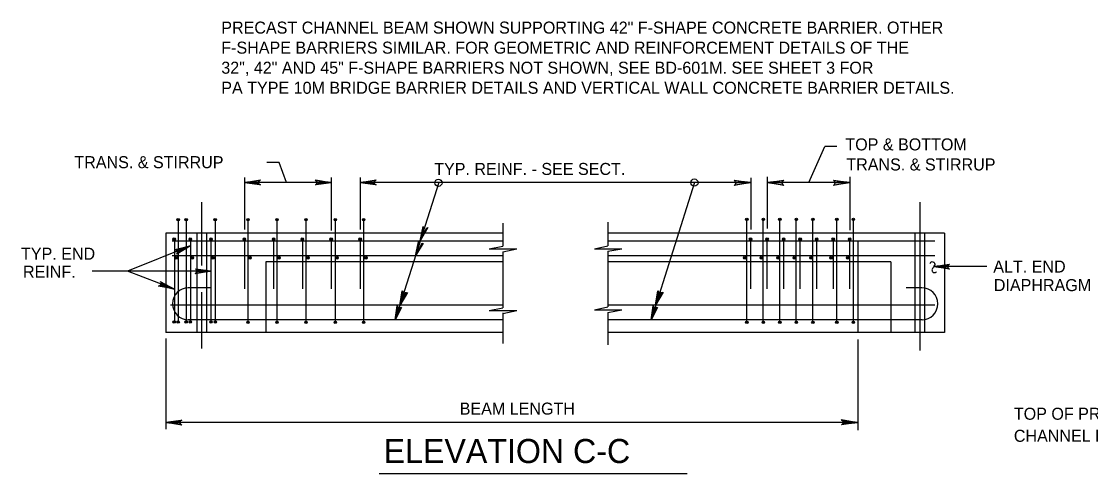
# Model space of a CAD drawing. Extents: x 642009 to 642864, y 298232 to 300014.
# Drawn here: x 642156.2 to 642423.1, y 299609.1 to 299721.8 of the extents above; entities that cross this region are included whole.
import ezdxf

# ---------------------------------------------------------------- set-up
doc = ezdxf.new("R2010")
doc.units = 0
doc.layers.add('1', color=7, linetype='Continuous')
doc.layers.add('2', color=7, linetype='Continuous')

msp = doc.modelspace()

# ---------------------------------------------------------------- linework, layer by layer
at = {"layer": '1'}
for centre in [(642260.31, 299681.61), (642324.2, 299681.65)]:
    msp.add_circle(centre, 0.903, dxfattribs=at)
at = {"layer": '2'}
for p, q in [((642352.76, 299681.67), (642356.76, 299690.67)), ((642359.76, 299690.67), (642356.76, 299690.67)), ((642220.57, 299686.62), (642217.45, 299686.62)), ((642222.38, 299681.67), (642220.57, 299686.62)), ((642211.88, 299682.92), (642211.88, 299669.92)), ((642233.51, 299681.67), (642211.88, 299681.67)), ((642233.51, 299682.92), (642233.51, 299669.67)), ((642240.76, 299682.92), (642240.76, 299669.92)), ((642338.26, 299681.67), (642240.76, 299681.67)), ((642260.38, 299681.67), (642249.51, 299647.42)), ((642324.26, 299681.67), (642313.38, 299647.42)), ((642338.26, 299682.8), (642338.26, 299669.92)), ((642342.38, 299683.05), (642342.38, 299670.17)), ((642363.01, 299681.67), (642342.38, 299681.67)), ((642363.01, 299683.05), (642363.01, 299669.8)), ((642201.2, 299676.74), (642201.2, 299660.99)), ((642380.45, 299676.74), (642380.45, 299639.82)), ((642195.36, 299672.52), (642195.36, 299646.92)), ((642197.36, 299672.52), (642197.36, 299646.92)), ((642204.62, 299672.52), (642204.62, 299646.92)), ((642212.76, 299672.52), (642212.76, 299646.92)), ((642220.01, 299672.52), (642220.01, 299646.92)), ((642227.26, 299672.52), (642227.26, 299646.92)), ((642234.51, 299672.52), (642234.51, 299646.92)), ((642241.63, 299672.52), (642241.63, 299646.92)), ((642276.38, 299671.55), (642276.38, 299665.8)), ((642302.63, 299671.8), (642302.63, 299665.92)), ((642337.26, 299646.92), (642337.26, 299672.52)), ((642341.38, 299646.92), (642341.38, 299672.52)), ((642345.51, 299646.92), (642345.51, 299672.52)), ((642349.63, 299646.92), (642349.63, 299672.52)), ((642353.76, 299646.92), (642353.76, 299672.52)), ((642359.76, 299646.92), (642359.76, 299672.52)), ((642363.88, 299646.92), (642363.88, 299672.52)), ((642276.38, 299669.05), (642192.26, 299669.05)), ((642192.26, 299669.05), (642192.26, 299668.05)), ((642192.26, 299668.42), (642192.26, 299644.3)), ((642194.42, 299667.55), (642194.42, 299646.92)), ((642198.45, 299667.55), (642198.45, 299646.92)), ((642200.01, 299669.05), (642200.01, 299644.3)), ((642202.39, 299669.05), (642202.39, 299644.3)), ((642203.51, 299667.55), (642203.51, 299646.92)), ((642211.88, 299667.55), (642211.88, 299655.17)), ((642219.13, 299667.55), (642219.13, 299655.17)), ((642226.38, 299667.55), (642226.38, 299655.17)), ((642233.51, 299667.55), (642233.51, 299655.17)), ((642240.76, 299667.55), (642240.76, 299655.17)), ((642386.63, 299669.05), (642302.63, 299669.05)), ((642338.26, 299655.17), (642338.26, 299667.55)), ((642342.38, 299655.17), (642342.38, 299667.55)), ((642346.51, 299655.17), (642346.51, 299667.55)), ((642350.63, 299655.17), (642350.63, 299667.55)), ((642354.76, 299655.17), (642354.76, 299667.55)), ((642358.88, 299655.17), (642358.88, 299667.55)), ((642363.01, 299655.17), (642363.01, 299667.55)), ((642379.26, 299669.05), (642379.26, 299644.3)), ((642381.63, 299669.05), (642381.63, 299644.3)), ((642386.63, 299669.05), (642386.63, 299644.3)), ((642198.45, 299665.91), (642182.68, 299659.55)), ((642276.38, 299667.05), (642193.82, 299667.05)), ((642273.01, 299665.17), (642276.38, 299665.8)), ((642273.01, 299665.17), (642279.88, 299665.17)), ((642276.38, 299664.42), (642279.88, 299665.17)), ((642299.26, 299665.17), (642302.63, 299665.92)), ((642299.26, 299665.17), (642306.13, 299665.17)), ((642384.21, 299667.05), (642302.63, 299667.05)), ((642302.63, 299664.55), (642306.13, 299665.17)), ((642365.01, 299667.05), (642365.01, 299644.3)), ((642276.38, 299663.42), (642193.82, 299663.42)), ((642276.38, 299664.42), (642276.38, 299650.42)), ((642302.63, 299664.55), (642302.63, 299650.67)), ((642384.21, 299663.42), (642302.63, 299663.42)), ((642197.51, 299659.55), (642173.88, 299659.55)), ((642194.42, 299655.04), (642182.68, 299659.55)), ((642203.51, 299659.55), (642197.51, 299659.55)), ((642217.26, 299661.92), (642217.26, 299644.3)), ((642276.38, 299661.92), (642217.26, 299661.92)), ((642373.26, 299661.92), (642302.63, 299661.92)), ((642373.26, 299661.92), (642373.26, 299644.3)), ((642397.19, 299660.72), (642383.91, 299660.72)), ((642203.61, 299655.42), (642197.88, 299655.42)), ((642201.2, 299654.32), (642201.2, 299640.32)), ((642380.97, 299655.41), (642377.07, 299655.41)), ((642276.38, 299651.05), (642193.42, 299651.05)), ((642273.01, 299649.8), (642276.38, 299650.42)), ((642273.01, 299649.8), (642279.88, 299649.8)), ((642276.38, 299649.05), (642279.88, 299649.8)), ((642276.38, 299649.17), (642276.38, 299641.55)), ((642299.26, 299649.92), (642302.63, 299650.67)), ((642299.26, 299649.92), (642306.13, 299649.92)), ((642384.21, 299651.05), (642302.63, 299651.05)), ((642302.63, 299649.3), (642306.13, 299649.92)), ((642302.63, 299649.3), (642302.63, 299641.17)), ((642276.38, 299647.42), (642197.88, 299647.42)), ((642381.03, 299647.42), (642302.63, 299647.42)), ((642276.38, 299644.3), (642192.26, 299644.3)), ((642386.63, 299644.3), (642302.63, 299644.3)), ((642192.26, 299642.8), (642192.26, 299620.17)), ((642365.01, 299642.55), (642365.01, 299619.92)), ((642365.01, 299621.8), (642192.38, 299621.8)), ((642245.53, 299609.1), (642322.4, 299609.1))]:
    msp.add_line(p, q, dxfattribs=at)
for points in [[(642215.63, 299681.17), (642215.51, 299681.42), (642211.88, 299681.67), (642215.63, 299681.17), (642215.88, 299681.05), (642211.88, 299681.67), (642215.51, 299681.8), (642215.63, 299682.05), (642211.88, 299681.67), (642215.88, 299682.3), (642215.63, 299682.05)], [(642229.76, 299682.05), (642229.88, 299681.8), (642233.51, 299681.67), (642229.76, 299682.05), (642229.63, 299682.3), (642233.51, 299681.67), (642229.88, 299681.42), (642229.76, 299681.17), (642233.51, 299681.67), (642229.63, 299681.05), (642229.76, 299681.17)], [(642244.51, 299681.17), (642244.38, 299681.42), (642240.76, 299681.67), (642244.51, 299681.17), (642244.76, 299681.05), (642240.76, 299681.67), (642244.38, 299681.8), (642244.51, 299682.05), (642240.76, 299681.67), (642244.76, 299682.3), (642244.51, 299682.05)], [(642334.32, 299682.05), (642334.32, 299681.86), (642338.26, 299681.67), (642334.32, 299682.05), (642334.13, 299682.23), (642338.26, 299681.67), (642334.51, 299681.48), (642334.32, 299681.11), (642338.26, 299681.67), (642334.13, 299680.92), (642334.32, 299681.11)], [(642346.32, 299681.11), (642346.13, 299681.48), (642342.38, 299681.67), (642346.32, 299681.11), (642346.51, 299680.92), (642342.38, 299681.67), (642346.13, 299681.86), (642346.32, 299682.05), (642342.38, 299681.67), (642346.51, 299682.23), (642346.32, 299682.05)], [(642359.07, 299682.05), (642359.07, 299681.86), (642363.01, 299681.67), (642359.07, 299682.05), (642358.88, 299682.23), (642363.01, 299681.67), (642359.26, 299681.48), (642359.07, 299681.11), (642363.01, 299681.67), (642358.88, 299680.92), (642359.07, 299681.11)], [(642257.52, 299670.3), (642257.22, 299670.17), (642255.72, 299667.17), (642257.52, 299670.3), (642257.67, 299670.42), (642255.72, 299667.17), (642256.77, 299670.3), (642256.47, 299670.55), (642255.72, 299667.17), (642256.47, 299670.67), (642256.47, 299670.55)], [(642194.8, 299664.92), (642195.01, 299664.74), (642198.45, 299665.91), (642194.8, 299664.92), (642194.52, 299664.94), (642198.45, 299665.91), (642195.15, 299664.4), (642195.13, 299664.12), (642198.45, 299665.91), (642195, 299663.79), (642195.13, 299664.12)], [(642256.39, 299666.38), (642256.09, 299666.38), (642254.59, 299663.38), (642256.39, 299666.38), (642256.54, 299666.51), (642254.59, 299663.38), (642255.64, 299666.51), (642255.49, 299666.63), (642254.59, 299663.38), (642255.34, 299666.88), (642255.49, 299666.63)], [(642199.76, 299660.05), (642199.89, 299659.8), (642203.51, 299659.55), (642199.76, 299660.05), (642199.64, 299660.17), (642203.51, 299659.55), (642199.89, 299659.42), (642199.76, 299659.17), (642203.51, 299659.55), (642199.64, 299658.92), (642199.76, 299659.17)], [(642387.66, 299660.22), (642387.53, 299660.47), (642383.91, 299660.72), (642387.66, 299660.22), (642387.91, 299660.09), (642383.91, 299660.72), (642387.53, 299660.84), (642387.66, 299661.09), (642383.91, 299660.72), (642387.91, 299661.34), (642387.66, 299661.09)], [(642191.07, 299656.8), (642191.1, 299656.52), (642194.42, 299655.04), (642191.07, 299656.8), (642190.87, 299657), (642194.42, 299655.04), (642190.97, 299656.17), (642190.77, 299655.98), (642194.42, 299655.04), (642190.45, 299655.83), (642190.77, 299655.98)], [(642252.33, 299654.13), (642252.03, 299654.13), (642250.68, 299651.01), (642252.33, 299654.13), (642252.63, 299654.26), (642250.68, 299651.01), (642251.73, 299654.13), (642251.43, 299654.38), (642250.68, 299651.01), (642251.28, 299654.63), (642251.43, 299654.38)], [(642316.14, 299654.17), (642315.84, 299654.17), (642314.49, 299651.05), (642316.14, 299654.17), (642316.44, 299654.3), (642314.49, 299651.05), (642315.39, 299654.17), (642315.24, 299654.42), (642314.49, 299651.05), (642315.09, 299654.67), (642315.24, 299654.42)], [(642251.01, 299650.55), (642250.63, 299650.42), (642249.51, 299647.42), (642251.01, 299650.55), (642251.13, 299650.55), (642249.51, 299647.42), (642250.38, 299650.55), (642250.13, 299650.67), (642249.51, 299647.42), (642250.01, 299650.92), (642250.13, 299650.67)], [(642314.76, 299650.55), (642314.51, 299650.42), (642313.38, 299647.42), (642314.76, 299650.55), (642315.01, 299650.55), (642313.38, 299647.42), (642314.26, 299650.55), (642314.01, 299650.67), (642313.38, 299647.42), (642313.88, 299650.92), (642314.01, 299650.67)], [(642196.01, 299621.42), (642195.88, 299621.67), (642192.26, 299621.8), (642196.01, 299621.42), (642196.26, 299621.17), (642192.26, 299621.8), (642195.88, 299622.05), (642196.01, 299622.3), (642192.26, 299621.8), (642196.26, 299622.42), (642196.01, 299622.3)], [(642361.07, 299622.36), (642361.26, 299622.17), (642365.01, 299621.8), (642361.07, 299622.36), (642360.88, 299622.55), (642365.01, 299621.8), (642361.26, 299621.61), (642361.07, 299621.42), (642365.01, 299621.8), (642360.88, 299621.23), (642361.07, 299621.42)]]:
    msp.add_lwpolyline(points, dxfattribs=at)
for centre, radius in [((642195.36, 299672.41), 0.31), ((642197.36, 299672.41), 0.31), ((642204.58, 299672.41), 0.31), ((642212.78, 299672.41), 0.31), ((642220.04, 299672.41), 0.31), ((642227.26, 299672.41), 0.31), ((642234.56, 299672.41), 0.31), ((642241.65, 299672.41), 0.31), ((642337.28, 299672.49), 0.31), ((642341.41, 299672.49), 0.31), ((642345.53, 299672.49), 0.31), ((642349.66, 299672.49), 0.31), ((642353.78, 299672.49), 0.31), ((642359.76, 299672.49), 0.31), ((642363.89, 299672.49), 0.31), ((642195.36, 299672.41), 0.171), ((642195.36, 299672.41), 0.0814), ((642197.36, 299672.41), 0.171), ((642197.36, 299672.41), 0.0814), ((642204.58, 299672.41), 0.171), ((642204.58, 299672.41), 0.0814), ((642212.78, 299672.41), 0.171), ((642212.78, 299672.41), 0.0814), ((642220.04, 299672.41), 0.171), ((642220.04, 299672.41), 0.0814), ((642227.26, 299672.41), 0.171), ((642227.26, 299672.41), 0.0814), ((642234.56, 299672.41), 0.171), ((642234.56, 299672.41), 0.0814), ((642241.65, 299672.41), 0.171), ((642241.65, 299672.41), 0.0814), ((642337.28, 299672.49), 0.171), ((642337.28, 299672.49), 0.0814), ((642341.41, 299672.49), 0.171), ((642341.41, 299672.49), 0.0814), ((642345.53, 299672.49), 0.171), ((642345.53, 299672.49), 0.0814), ((642349.66, 299672.49), 0.171), ((642349.66, 299672.49), 0.0814), ((642353.78, 299672.49), 0.171), ((642353.78, 299672.49), 0.0814), ((642359.76, 299672.49), 0.171), ((642359.76, 299672.49), 0.0814), ((642363.89, 299672.49), 0.171), ((642363.89, 299672.49), 0.0814), ((642194.36, 299667.54), 0.31), ((642194.36, 299667.54), 0.171), ((642194.36, 299667.54), 0.0814), ((642198.39, 299667.54), 0.31), ((642198.39, 299667.54), 0.171), ((642198.39, 299667.54), 0.0814), ((642203.55, 299667.54), 0.31), ((642203.55, 299667.54), 0.171), ((642203.55, 299667.54), 0.0814), ((642211.89, 299667.54), 0.31), ((642211.89, 299667.54), 0.171), ((642211.89, 299667.54), 0.0814), ((642219.18, 299667.54), 0.31), ((642219.18, 299667.54), 0.171), ((642219.18, 299667.54), 0.0814), ((642226.33, 299667.54), 0.31), ((642226.33, 299667.54), 0.171), ((642226.33, 299667.54), 0.0814), ((642233.55, 299667.54), 0.31), ((642233.55, 299667.54), 0.171), ((642233.55, 299667.54), 0.0814), ((642240.77, 299667.54), 0.31), ((642240.77, 299667.54), 0.171), ((642240.77, 299667.54), 0.0814), ((642338.22, 299667.54), 0.31), ((642338.22, 299667.54), 0.171), ((642338.22, 299667.54), 0.0814), ((642342.35, 299667.54), 0.31), ((642342.35, 299667.54), 0.171), ((642342.35, 299667.54), 0.0814), ((642346.47, 299667.54), 0.31), ((642346.47, 299667.54), 0.171), ((642346.47, 299667.54), 0.0814), ((642350.6, 299667.54), 0.31), ((642350.6, 299667.54), 0.171), ((642350.6, 299667.54), 0.0814), ((642354.72, 299667.54), 0.31), ((642354.72, 299667.54), 0.171), ((642354.72, 299667.54), 0.0814), ((642358.85, 299667.54), 0.31), ((642358.85, 299667.54), 0.171), ((642358.85, 299667.54), 0.0814), ((642362.97, 299667.54), 0.31), ((642362.97, 299667.54), 0.171), ((642362.97, 299667.54), 0.0814), ((642194.88, 299662.9), 0.31), ((642194.88, 299662.9), 0.171), ((642198.91, 299662.9), 0.31), ((642198.91, 299662.9), 0.171), ((642204.07, 299662.9), 0.31), ((642204.07, 299662.9), 0.171), ((642204.07, 299662.9), 0.0814), ((642213.26, 299662.9), 0.31), ((642213.26, 299662.9), 0.171), ((642213.26, 299662.9), 0.0814), ((642220.5, 299662.9), 0.31), ((642220.5, 299662.9), 0.171), ((642220.5, 299662.9), 0.0814), ((642227.73, 299662.9), 0.31), ((642227.73, 299662.9), 0.171), ((642227.73, 299662.9), 0.0814), ((642234.96, 299662.9), 0.31), ((642234.96, 299662.9), 0.171), ((642234.96, 299662.9), 0.0814), ((642242.19, 299662.9), 0.31), ((642242.19, 299662.9), 0.171), ((642242.19, 299662.9), 0.0814), ((642336.8, 299662.9), 0.31), ((642336.8, 299662.9), 0.171), ((642336.8, 299662.9), 0.0814), ((642340.93, 299662.9), 0.31), ((642340.93, 299662.9), 0.171), ((642340.93, 299662.9), 0.0814), ((642345.05, 299662.9), 0.31), ((642345.05, 299662.9), 0.171), ((642345.05, 299662.9), 0.0814), ((642349.18, 299662.9), 0.31), ((642349.18, 299662.9), 0.171), ((642349.18, 299662.9), 0.0814), ((642353.3, 299662.9), 0.31), ((642353.3, 299662.9), 0.171), ((642353.3, 299662.9), 0.0814), ((642358.33, 299662.9), 0.31), ((642358.33, 299662.9), 0.171), ((642358.33, 299662.9), 0.0814), ((642362.45, 299662.9), 0.31), ((642362.45, 299662.9), 0.171), ((642362.45, 299662.9), 0.0814), ((642194.36, 299646.91), 0.31), ((642194.36, 299646.91), 0.171), ((642194.36, 299646.91), 0.0814), ((642195.34, 299646.91), 0.31), ((642195.34, 299646.91), 0.171), ((642195.34, 299646.91), 0.0814), ((642197.35, 299646.91), 0.31), ((642197.35, 299646.91), 0.171), ((642197.35, 299646.91), 0.0814), ((642198.39, 299646.91), 0.31), ((642198.39, 299646.91), 0.171), ((642198.39, 299646.91), 0.0814), ((642203.55, 299646.91), 0.31), ((642203.55, 299646.91), 0.171), ((642203.55, 299646.91), 0.0814), ((642204.65, 299646.91), 0.31), ((642204.65, 299646.91), 0.171), ((642204.65, 299646.91), 0.0814), ((642212.78, 299646.83), 0.31), ((642212.78, 299646.83), 0.171), ((642212.78, 299646.83), 0.0814), ((642220.04, 299646.83), 0.31), ((642220.04, 299646.83), 0.171), ((642220.04, 299646.83), 0.0814), ((642227.26, 299646.83), 0.31), ((642227.26, 299646.83), 0.171), ((642227.26, 299646.83), 0.0814), ((642234.56, 299646.83), 0.31), ((642234.56, 299646.83), 0.171), ((642234.56, 299646.83), 0.0814), ((642241.65, 299646.83), 0.31), ((642241.65, 299646.83), 0.171), ((642241.65, 299646.83), 0.0814), ((642337.28, 299646.83), 0.31), ((642337.28, 299646.83), 0.171), ((642337.28, 299646.83), 0.0814), ((642341.41, 299646.83), 0.31), ((642341.41, 299646.83), 0.171), ((642341.41, 299646.83), 0.0814), ((642345.53, 299646.83), 0.31), ((642345.53, 299646.83), 0.171), ((642345.53, 299646.83), 0.0814), ((642349.66, 299646.83), 0.31), ((642349.66, 299646.83), 0.171), ((642349.66, 299646.83), 0.0814), ((642353.78, 299646.83), 0.31), ((642353.78, 299646.83), 0.171), ((642353.78, 299646.83), 0.0814), ((642359.76, 299646.83), 0.31), ((642359.76, 299646.83), 0.171), ((642359.76, 299646.83), 0.0814), ((642363.89, 299646.83), 0.31), ((642363.89, 299646.83), 0.171), ((642363.89, 299646.83), 0.0814)]:
    msp.add_circle(centre, radius, dxfattribs=at)
for centre, start, end in [((642197.94, 299651.43), 90.0597, 269.1504), ((642380.97, 299651.42), 270.8496, 89.9403)]:
    msp.add_arc(centre, 4, start, end, dxfattribs=at)
msp.add_spline([(642383.04, 299661.47), (642383.21, 299661.85), (642383.91, 299661.84), (642384.03, 299661.72), (642384.16, 299661.47), (642384.2, 299661.24), (642384.15, 299661.09), (642384.07, 299660.94), (642383.9, 299660.59), (642383.7, 299660.33), (642383.62, 299660.18), (642383.52, 299660.03), (642383.52, 299659.7), (642383.64, 299659.45), (642383.74, 299659.28), (642383.91, 299659.22), (642384.4, 299659.27), (642384.6, 299659.46)], degree=3, dxfattribs=at)

# ---------------------------------------------------------------- texts
for s, height, p in [('PRECAST CHANNEL BEAM SHOWN SUPPORTING 42" F-SHAPE CONCRETE BARRIER. OTHER ', 3, (642206.12, 299718.79)), ('F-SHAPE BARRIERS SIMILAR. FOR GEOMETRIC AND REINFORCEMENT DETAILS OF THE ', 3, (642206.12, 299713.79)), ('32", 42" AND 45" F-SHAPE BARRIERS NOT SHOWN, SEE BD-601M. SEE SHEET 3 FOR ', 3, (642206.12, 299708.79)), ('PA TYPE 10M BRIDGE BARRIER DETAILS AND VERTICAL WALL CONCRETE BARRIER DETAILS.', 3, (642206.12, 299703.79)), ('TOP & BOTTOM', 3, (642361.88, 299689.67)), ('TRANS. & STIRRUP', 3, (642169.45, 299685.24)), ('TYP. REINF. - SEE SECT.', 3, (642259.26, 299683.55)), ('TRANS. & STIRRUP', 3, (642362.13, 299684.67)), ('TYP. END', 3, (642156.13, 299662.42)), ('ALT. END', 3, (642398.81, 299659.22)), ('REINF.', 3, (642156.63, 299657.92)), ('DIAPHRAGM', 3, (642398.94, 299654.59)), ('BEAM LENGTH', 3, (642265.63, 299623.8)), ('TOP OF PRECAST', 3, (642403.94, 299622.52)), ('CHANNEL BEAM', 3, (642403.94, 299617.02)), ('ELEVATION C-C', 6, (642246.65, 299611.73))]:
    msp.add_text(s, height=height, dxfattribs=at).set_placement(p)

doc.saveas('drawing.dxf')
